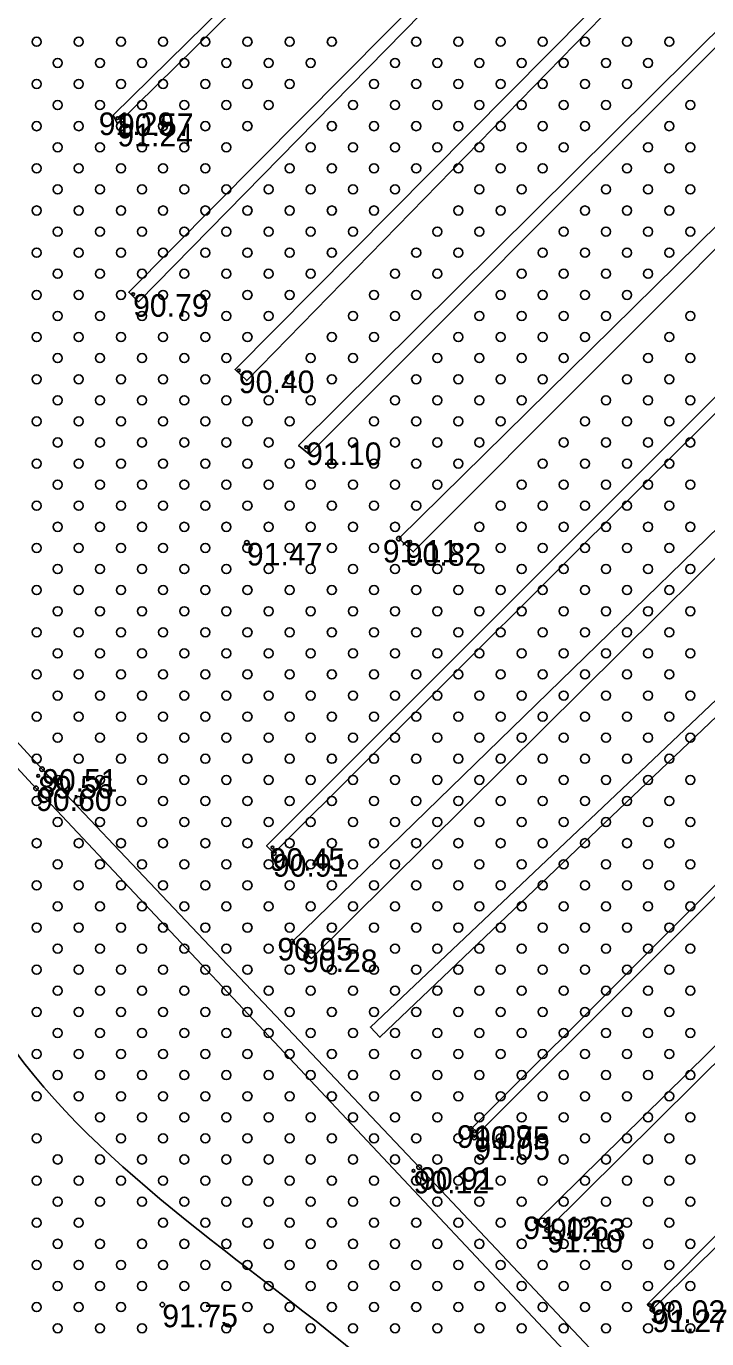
# Model space of a CAD drawing. Extents: x 316000 to 728450, y 314368 to 726000.
# Drawn here: x 725653.3 to 725766.2, y 315232.8 to 315450.6 of the extents above; entities that cross this region are included whole.
import ezdxf

# ---------------------------------------------------------------- set-up
doc = ezdxf.new("R2010")
doc.units = 0
for name, color, linetype in [('HIDG_ELEM_####_####_#', 7, 'Continuous'), ('HIDG_GRAV_####_####_#', 7, 'Continuous'), ('RELJ_AATZ_####_TKST_#', 7, 'Continuous'), ('RELJ_ELEM_####_####_#', 7, 'Continuous'), ('RELJ_HORZ_PAMT_####_#', 7, 'Continuous'), ('RELJ_NOGA_####_####_#', 7, 'Continuous'), ('TERT_ELEM_####_####_#', 7, 'Continuous')]:
    doc.layers.add(name, color=color, linetype=linetype)

msp = doc.modelspace()

# ---------------------------------------------------------------- linework, layer by layer
at = {"layer": 'HIDG_ELEM_####_####_#'}
for centre in [(725668.42, 315435.34), (725671.01, 315406.12), (725688.56, 315393.44), (725699.75, 315380.74), (725717, 315365.02), (725655.26, 315326.16), (725694.15, 315314.3), (725699.66, 315297.94), (725727.69, 315267.18), (725717.56, 315260.63), (725739.58, 315252.21), (725756.81, 315238.31)]:
    msp.add_circle(centre, 0.225, dxfattribs=at)
at = {"layer": 'HIDG_GRAV_####_####_#'}
for points in [[(725789.82, 315555.77), (725790.78, 315554.71), (725668.4, 315434.39), (725667.72, 315435.8), (725789.82, 315555.77)], [(725806.05, 315543.31), (725806.83, 315542.39), (725671.92, 315404.85), (725670.3, 315406.43), (725806.05, 315543.31)], [(725811.36, 315518.13), (725812.41, 315517.33), (725689.87, 315391.76), (725687.94, 315393.64), (725811.36, 315518.13)], [(725828.98, 315510.46), (725830.11, 315509.58), (725700.23, 315379.56), (725698.49, 315381.01), (725828.98, 315510.46)], [(725715.11, 315365.54), (725717.51, 315363.33), (725844.02, 315490.17), (725842.75, 315491.26), (725715.11, 315365.54)], [(725860.37, 315481.73), (725862.24, 315480.66), (725694.37, 315313.35), (725693.18, 315314.53), (725860.37, 315481.73)], [(725870.88, 315467.83), (725872.5, 315466.68), (725822.42, 315416.58), (725700.62, 315295.88), (725697.4, 315298.64), (725820.94, 315418.78), (725870.88, 315467.83)], [(725885.7, 315450.41), (725886.74, 315449.26), (725711.99, 315282.8), (725710.4, 315284.47), (725885.7, 315450.41)], [(725655.9, 315327.28), (725551.95, 315440.48)], [(725898.3, 315438.42), (725899.18, 315437.36), (725727.65, 315266.16), (725727.06, 315267.56), (725898.3, 315438.42)], [(725550.64, 315437.37), (725654.91, 315324.09), (725793.17, 315176.93), (726030.02, 314925.45), (726035.1, 314929.94), (725796.17, 315178.83)], [(725738.04, 315252.21), (725739.75, 315250.83), (725917.08, 315426.55), (725915.72, 315427.14), (725738.04, 315252.21)], [(725927.99, 315410.77), (725929.99, 315408.89), (725850.79, 315329.18), (725850.79, 315329.17), (725757.22, 315237.64), (725756.41, 315238.37), (725756.35, 315238.43), (725927.99, 315410.77)], [(725655.9, 315327.28), (725718.48, 315261.22), (725796.17, 315178.83)]]:
    msp.add_lwpolyline(points, dxfattribs=at)
at = {"layer": 'RELJ_ELEM_####_####_#'}
for centre in [(725689.89, 315364.84), (725715.11, 315365.54), (725655.9, 315327.28), (725654.91, 315324.09), (725694.37, 315313.35), (725697.4, 315298.64), (725727.06, 315267.56), (725727.65, 315266.16), (725718.48, 315261.22), (725738.04, 315252.21), (725739.75, 315250.83), (725675.86, 315238.41), (725757.19, 315237.6)]:
    msp.add_circle(centre, 0.375, dxfattribs=at)
at = {"layer": 'RELJ_HORZ_PAMT_####_#'}
msp.add_spline([(726081.57, 315247.05), (726057.5, 315241.5), (726036.5, 315213.5), (725977, 315161), (725966.5, 315108.5), (725903.5, 315045.5), (725862.12, 315076.6), (725805.5, 315130), (725759.7, 315178.88), (725709.89, 315228.8), (725646.99, 315287.19), (725634.68, 315314.96), (725629.04, 315327.48), (725557.35, 315340.26), (725478.3, 315344.16)], degree=3, dxfattribs=at)
at = {"layer": 'RELJ_NOGA_####_####_#'}
for points in [[(726259.12, 315084.51), (726262.72, 315089.26), (726261.56, 315090.84), (726260.2, 315092.42), (726257.29, 315095.53), (726218.91, 315136.38), (726180.31, 315176.84), (726128.67, 315229.97), (726063.7, 315298.11), (725999.9, 315366.09), (725937.21, 315432.09), (725876.35, 315495.23), (725810.58, 315563.08), (725744.7, 315632.91)], [(725740.86, 315626.98), (725805.54, 315558.12), (725870.39, 315491.15), (725932.8, 315426.8), (725994.98, 315360.84), (726059.66, 315292.12), (726075.75, 315275.46), (726092.08, 315259.04), (726108.47, 315242.67), (726124.69, 315226.14), (726193.27, 315154.03), (726250.06, 315092.6), (726256.32, 315085.83), (726258.82, 315084.29), (726259.12, 315084.51)]]:
    msp.add_spline(points, degree=3, dxfattribs=at)
at = {"layer": 'TERT_ELEM_####_####_#'}
for centre in [(725655, 315448), (725662, 315448), (725669, 315448), (725676, 315448), (725683, 315448), (725690, 315448), (725697, 315448), (725704, 315448), (725718, 315448), (725725, 315448), (725732, 315448), (725739, 315448), (725746, 315448), (725753, 315448), (725760, 315448), (725658.5, 315444.5), (725665.5, 315444.5), (725672.5, 315444.5), (725679.5, 315444.5), (725686.5, 315444.5), (725693.5, 315444.5), (725700.5, 315444.5), (725714.5, 315444.5), (725721.5, 315444.5), (725728.5, 315444.5), (725735.5, 315444.5), (725742.5, 315444.5), (725749.5, 315444.5), (725756.5, 315444.5), (725655, 315441), (725662, 315441), (725669, 315441), (725676, 315441), (725683, 315441), (725690, 315441), (725697, 315441), (725711, 315441), (725718, 315441), (725725, 315441), (725732, 315441), (725739, 315441), (725746, 315441), (725753, 315441), (725658.5, 315437.5), (725665.5, 315437.5), (725672.5, 315437.5), (725679.5, 315437.5), (725686.5, 315437.5), (725693.5, 315437.5), (725707.5, 315437.5), (725714.5, 315437.5), (725721.5, 315437.5), (725728.5, 315437.5), (725735.5, 315437.5), (725742.5, 315437.5), (725749.5, 315437.5), (725763.5, 315437.5), (725655, 315434), (725662, 315434), (725669, 315434), (725676, 315434), (725683, 315434), (725690, 315434), (725704, 315434), (725711, 315434), (725718, 315434), (725725, 315434), (725732, 315434), (725739, 315434), (725746, 315434), (725760, 315434), (725658.5, 315430.5), (725665.5, 315430.5), (725672.5, 315430.5), (725679.5, 315430.5), (725686.5, 315430.5), (725700.5, 315430.5), (725707.5, 315430.5), (725714.5, 315430.5), (725721.5, 315430.5), (725728.5, 315430.5), (725735.5, 315430.5), (725742.5, 315430.5), (725756.5, 315430.5), (725763.5, 315430.5), (725655, 315427), (725662, 315427), (725669, 315427), (725676, 315427), (725683, 315427), (725697, 315427), (725704, 315427), (725711, 315427), (725718, 315427), (725725, 315427), (725732, 315427), (725739, 315427), (725753, 315427), (725760, 315427), (725658.5, 315423.5), (725665.5, 315423.5), (725672.5, 315423.5), (725679.5, 315423.5), (725686.5, 315423.5), (725693.5, 315423.5), (725700.5, 315423.5), (725707.5, 315423.5), (725714.5, 315423.5), (725728.5, 315423.5), (725735.5, 315423.5), (725749.5, 315423.5), (725756.5, 315423.5), (725763.5, 315423.5), (725655, 315420), (725662, 315420), (725669, 315420), (725676, 315420), (725683, 315420), (725690, 315420), (725697, 315420), (725704, 315420), (725711, 315420), (725725, 315420), (725732, 315420), (725746, 315420), (725753, 315420), (725760, 315420), (725658.5, 315416.5), (725665.5, 315416.5), (725672.5, 315416.5), (725679.5, 315416.5), (725686.5, 315416.5), (725693.5, 315416.5), (725700.5, 315416.5), (725707.5, 315416.5), (725721.5, 315416.5), (725728.5, 315416.5), (725742.5, 315416.5), (725749.5, 315416.5), (725756.5, 315416.5), (725763.5, 315416.5), (725655, 315413), (725662, 315413), (725669, 315413), (725676, 315413), (725683, 315413), (725690, 315413), (725697, 315413), (725704, 315413), (725718, 315413), (725725, 315413), (725739, 315413), (725746, 315413), (725753, 315413), (725760, 315413), (725658.5, 315409.5), (725665.5, 315409.5), (725672.5, 315409.5), (725679.5, 315409.5), (725686.5, 315409.5), (725693.5, 315409.5), (725700.5, 315409.5), (725714.5, 315409.5), (725721.5, 315409.5), (725735.5, 315409.5), (725742.5, 315409.5), (725749.5, 315409.5), (725756.5, 315409.5), (725655, 315406), (725662, 315406), (725669, 315406), (725676, 315406), (725683, 315406), (725690, 315406), (725697, 315406), (725711, 315406), (725718, 315406), (725732, 315406), (725739, 315406), (725746, 315406), (725753, 315406), (725658.5, 315402.5), (725665.5, 315402.5), (725672.5, 315402.5), (725679.5, 315402.5), (725686.5, 315402.5), (725693.5, 315402.5), (725707.5, 315402.5), (725714.5, 315402.5), (725728.5, 315402.5), (725735.5, 315402.5), (725742.5, 315402.5), (725749.5, 315402.5), (725763.5, 315402.5), (725655, 315399), (725662, 315399), (725669, 315399), (725676, 315399), (725683, 315399), (725690, 315399), (725704, 315399), (725711, 315399), (725725, 315399), (725732, 315399), (725739, 315399), (725746, 315399), (725760, 315399), (725658.5, 315395.5), (725665.5, 315395.5), (725672.5, 315395.5), (725679.5, 315395.5), (725686.5, 315395.5), (725700.5, 315395.5), (725707.5, 315395.5), (725721.5, 315395.5), (725728.5, 315395.5), (725735.5, 315395.5), (725742.5, 315395.5), (725756.5, 315395.5), (725763.5, 315395.5), (725655, 315392), (725662, 315392), (725669, 315392), (725676, 315392), (725683, 315392), (725697, 315392), (725704, 315392), (725718, 315392), (725725, 315392), (725732, 315392), (725739, 315392), (725753, 315392), (725760, 315392), (725658.5, 315388.5), (725665.5, 315388.5), (725672.5, 315388.5), (725679.5, 315388.5), (725686.5, 315388.5), (725693.5, 315388.5), (725700.5, 315388.5), (725714.5, 315388.5), (725721.5, 315388.5), (725728.5, 315388.5), (725735.5, 315388.5), (725749.5, 315388.5), (725756.5, 315388.5), (725763.5, 315388.5), (725655, 315385), (725662, 315385), (725669, 315385), (725676, 315385), (725683, 315385), (725690, 315385), (725697, 315385), (725711, 315385), (725718, 315385), (725725, 315385), (725732, 315385), (725746, 315385), (725753, 315385), (725760, 315385), (725658.5, 315381.5), (725665.5, 315381.5), (725672.5, 315381.5), (725679.5, 315381.5), (725686.5, 315381.5), (725693.5, 315381.5), (725707.5, 315381.5), (725714.5, 315381.5), (725721.5, 315381.5), (725728.5, 315381.5), (725742.5, 315381.5), (725749.5, 315381.5), (725756.5, 315381.5), (725763.5, 315381.5), (725655, 315378), (725662, 315378), (725669, 315378), (725676, 315378), (725683, 315378), (725690, 315378), (725697, 315378), (725704, 315378), (725711, 315378), (725718, 315378), (725725, 315378), (725739, 315378), (725746, 315378), (725753, 315378), (725760, 315378), (725658.5, 315374.5), (725665.5, 315374.5), (725672.5, 315374.5), (725679.5, 315374.5), (725686.5, 315374.5), (725693.5, 315374.5), (725700.5, 315374.5), (725707.5, 315374.5), (725714.5, 315374.5), (725721.5, 315374.5), (725735.5, 315374.5), (725742.5, 315374.5), (725749.5, 315374.5), (725756.5, 315374.5), (725763.5, 315374.5), (725655, 315371), (725662, 315371), (725669, 315371), (725676, 315371), (725683, 315371), (725690, 315371), (725697, 315371), (725704, 315371), (725711, 315371), (725718, 315371), (725732, 315371), (725739, 315371), (725746, 315371), (725753, 315371), (725760, 315371), (725658.5, 315367.5), (725665.5, 315367.5), (725672.5, 315367.5), (725679.5, 315367.5), (725686.5, 315367.5), (725693.5, 315367.5), (725700.5, 315367.5), (725707.5, 315367.5), (725714.5, 315367.5), (725728.5, 315367.5), (725735.5, 315367.5), (725742.5, 315367.5), (725749.5, 315367.5), (725756.5, 315367.5), (725763.5, 315367.5), (725655, 315364), (725662, 315364), (725669, 315364), (725676, 315364), (725683, 315364), (725690, 315364), (725697, 315364), (725704, 315364), (725711, 315364), (725725, 315364), (725732, 315364), (725739, 315364), (725746, 315364), (725753, 315364), (725760, 315364), (725658.5, 315360.5), (725665.5, 315360.5), (725672.5, 315360.5), (725679.5, 315360.5), (725686.5, 315360.5), (725693.5, 315360.5), (725700.5, 315360.5), (725707.5, 315360.5), (725714.5, 315360.5), (725721.5, 315360.5), (725728.5, 315360.5), (725735.5, 315360.5), (725742.5, 315360.5), (725749.5, 315360.5), (725756.5, 315360.5), (725763.5, 315360.5), (725655, 315357), (725662, 315357), (725669, 315357), (725676, 315357), (725683, 315357), (725690, 315357), (725697, 315357), (725704, 315357), (725711, 315357), (725718, 315357), (725725, 315357), (725732, 315357), (725739, 315357), (725746, 315357), (725753, 315357), (725760, 315357), (725658.5, 315353.5), (725665.5, 315353.5), (725672.5, 315353.5), (725679.5, 315353.5), (725686.5, 315353.5), (725693.5, 315353.5), (725700.5, 315353.5), (725707.5, 315353.5), (725714.5, 315353.5), (725721.5, 315353.5), (725728.5, 315353.5), (725735.5, 315353.5), (725742.5, 315353.5), (725749.5, 315353.5), (725756.5, 315353.5), (725763.5, 315353.5), (725655, 315350), (725662, 315350), (725669, 315350), (725676, 315350), (725683, 315350), (725690, 315350), (725697, 315350), (725704, 315350), (725711, 315350), (725718, 315350), (725725, 315350), (725732, 315350), (725739, 315350), (725746, 315350), (725753, 315350), (725760, 315350), (725658.5, 315346.5), (725665.5, 315346.5), (725672.5, 315346.5), (725679.5, 315346.5), (725686.5, 315346.5), (725693.5, 315346.5), (725700.5, 315346.5), (725707.5, 315346.5), (725714.5, 315346.5), (725721.5, 315346.5), (725728.5, 315346.5), (725735.5, 315346.5), (725742.5, 315346.5), (725749.5, 315346.5), (725756.5, 315346.5), (725763.5, 315346.5), (725655, 315343), (725662, 315343), (725669, 315343), (725676, 315343), (725683, 315343), (725690, 315343), (725697, 315343), (725704, 315343), (725711, 315343), (725718, 315343), (725725, 315343), (725732, 315343), (725739, 315343), (725746, 315343), (725753, 315343), (725760, 315343), (725658.5, 315339.5), (725665.5, 315339.5), (725672.5, 315339.5), (725679.5, 315339.5), (725686.5, 315339.5), (725693.5, 315339.5), (725700.5, 315339.5), (725707.5, 315339.5), (725714.5, 315339.5), (725721.5, 315339.5), (725728.5, 315339.5), (725735.5, 315339.5), (725742.5, 315339.5), (725749.5, 315339.5), (725756.5, 315339.5), (725763.5, 315339.5), (725655, 315336), (725662, 315336), (725669, 315336), (725676, 315336), (725683, 315336), (725690, 315336), (725697, 315336), (725704, 315336), (725711, 315336), (725718, 315336), (725725, 315336), (725732, 315336), (725739, 315336), (725746, 315336), (725753, 315336), (725760, 315336), (725658.5, 315332.5), (725665.5, 315332.5), (725672.5, 315332.5), (725679.5, 315332.5), (725686.5, 315332.5), (725693.5, 315332.5), (725700.5, 315332.5), (725707.5, 315332.5), (725714.5, 315332.5), (725721.5, 315332.5), (725728.5, 315332.5), (725735.5, 315332.5), (725742.5, 315332.5), (725749.5, 315332.5), (725756.5, 315332.5), (725763.5, 315332.5), (725655, 315329), (725662, 315329), (725669, 315329), (725676, 315329), (725683, 315329), (725690, 315329), (725697, 315329), (725704, 315329), (725711, 315329), (725718, 315329), (725725, 315329), (725732, 315329), (725739, 315329), (725746, 315329), (725753, 315329), (725760, 315329), (725658.5, 315325.5), (725665.5, 315325.5), (725672.5, 315325.5), (725679.5, 315325.5), (725686.5, 315325.5), (725693.5, 315325.5), (725700.5, 315325.5), (725707.5, 315325.5), (725714.5, 315325.5), (725721.5, 315325.5), (725728.5, 315325.5), (725735.5, 315325.5), (725742.5, 315325.5), (725749.5, 315325.5), (725756.5, 315325.5), (725763.5, 315325.5), (725655, 315322), (725662, 315322), (725669, 315322), (725676, 315322), (725683, 315322), (725690, 315322), (725697, 315322), (725704, 315322), (725711, 315322), (725718, 315322), (725725, 315322), (725732, 315322), (725739, 315322), (725746, 315322), (725753, 315322), (725760, 315322), (725658.5, 315318.5), (725665.5, 315318.5), (725672.5, 315318.5), (725679.5, 315318.5), (725686.5, 315318.5), (725693.5, 315318.5), (725700.5, 315318.5), (725707.5, 315318.5), (725714.5, 315318.5), (725721.5, 315318.5), (725728.5, 315318.5), (725735.5, 315318.5), (725742.5, 315318.5), (725749.5, 315318.5), (725756.5, 315318.5), (725763.5, 315318.5), (725655, 315315), (725662, 315315), (725669, 315315), (725676, 315315), (725683, 315315), (725690, 315315), (725697, 315315), (725704, 315315), (725711, 315315), (725718, 315315), (725725, 315315), (725732, 315315), (725739, 315315), (725746, 315315), (725753, 315315), (725760, 315315), (725658.5, 315311.5), (725665.5, 315311.5), (725672.5, 315311.5), (725679.5, 315311.5), (725686.5, 315311.5), (725693.5, 315311.5), (725700.5, 315311.5), (725707.5, 315311.5), (725714.5, 315311.5), (725721.5, 315311.5), (725728.5, 315311.5), (725735.5, 315311.5), (725742.5, 315311.5), (725749.5, 315311.5), (725756.5, 315311.5), (725763.5, 315311.5), (725655, 315308), (725662, 315308), (725669, 315308), (725676, 315308), (725683, 315308), (725690, 315308), (725697, 315308), (725704, 315308), (725711, 315308), (725718, 315308), (725725, 315308), (725732, 315308), (725739, 315308), (725746, 315308), (725753, 315308), (725760, 315308), (725658.5, 315304.5), (725665.5, 315304.5), (725672.5, 315304.5), (725679.5, 315304.5), (725686.5, 315304.5), (725693.5, 315304.5), (725700.5, 315304.5), (725707.5, 315304.5), (725714.5, 315304.5), (725721.5, 315304.5), (725728.5, 315304.5), (725735.5, 315304.5), (725742.5, 315304.5), (725749.5, 315304.5), (725756.5, 315304.5), (725763.5, 315304.5), (725655, 315301), (725662, 315301), (725669, 315301), (725676, 315301), (725683, 315301), (725690, 315301), (725697, 315301), (725704, 315301), (725711, 315301), (725718, 315301), (725725, 315301), (725732, 315301), (725739, 315301), (725746, 315301), (725753, 315301), (725760, 315301), (725658.5, 315297.5), (725665.5, 315297.5), (725672.5, 315297.5), (725679.5, 315297.5), (725686.5, 315297.5), (725693.5, 315297.5), (725700.5, 315297.5), (725707.5, 315297.5), (725714.5, 315297.5), (725721.5, 315297.5), (725728.5, 315297.5), (725735.5, 315297.5), (725742.5, 315297.5), (725749.5, 315297.5), (725756.5, 315297.5), (725763.5, 315297.5), (725655, 315294), (725662, 315294), (725669, 315294), (725676, 315294), (725683, 315294), (725690, 315294), (725697, 315294), (725704, 315294), (725711, 315294), (725718, 315294), (725725, 315294), (725732, 315294), (725739, 315294), (725746, 315294), (725753, 315294), (725760, 315294), (725658.5, 315290.5), (725665.5, 315290.5), (725672.5, 315290.5), (725679.5, 315290.5), (725686.5, 315290.5), (725693.5, 315290.5), (725700.5, 315290.5), (725707.5, 315290.5), (725714.5, 315290.5), (725721.5, 315290.5), (725728.5, 315290.5), (725735.5, 315290.5), (725742.5, 315290.5), (725749.5, 315290.5), (725756.5, 315290.5), (725763.5, 315290.5), (725655, 315287), (725662, 315287), (725669, 315287), (725676, 315287), (725683, 315287), (725690, 315287), (725697, 315287), (725704, 315287), (725711, 315287), (725718, 315287), (725725, 315287), (725732, 315287), (725739, 315287), (725746, 315287), (725753, 315287), (725760, 315287), (725658.5, 315283.5), (725665.5, 315283.5), (725672.5, 315283.5), (725679.5, 315283.5), (725686.5, 315283.5), (725693.5, 315283.5), (725700.5, 315283.5), (725707.5, 315283.5), (725714.5, 315283.5), (725721.5, 315283.5), (725728.5, 315283.5), (725735.5, 315283.5), (725742.5, 315283.5), (725749.5, 315283.5), (725756.5, 315283.5), (725763.5, 315283.5), (725655, 315280), (725662, 315280), (725669, 315280), (725676, 315280), (725683, 315280), (725690, 315280), (725697, 315280), (725704, 315280), (725711, 315280), (725718, 315280), (725725, 315280), (725732, 315280), (725739, 315280), (725746, 315280), (725753, 315280), (725760, 315280), (725658.5, 315276.5), (725665.5, 315276.5), (725672.5, 315276.5), (725679.5, 315276.5), (725686.5, 315276.5), (725693.5, 315276.5), (725700.5, 315276.5), (725707.5, 315276.5), (725714.5, 315276.5), (725721.5, 315276.5), (725728.5, 315276.5), (725735.5, 315276.5), (725742.5, 315276.5), (725749.5, 315276.5), (725756.5, 315276.5), (725763.5, 315276.5), (725655, 315273), (725662, 315273), (725669, 315273), (725676, 315273), (725683, 315273), (725690, 315273), (725697, 315273), (725704, 315273), (725711, 315273), (725718, 315273), (725725, 315273), (725732, 315273), (725739, 315273), (725746, 315273), (725753, 315273), (725760, 315273), (725665.5, 315269.5), (725672.5, 315269.5), (725679.5, 315269.5), (725686.5, 315269.5), (725693.5, 315269.5), (725700.5, 315269.5), (725707.5, 315269.5), (725714.5, 315269.5), (725721.5, 315269.5), (725728.5, 315269.5), (725735.5, 315269.5), (725742.5, 315269.5), (725749.5, 315269.5), (725756.5, 315269.5), (725763.5, 315269.5), (725655, 315266), (725669, 315266), (725676, 315266), (725683, 315266), (725690, 315266), (725697, 315266), (725704, 315266), (725711, 315266), (725718, 315266), (725725, 315266), (725732, 315266), (725739, 315266), (725746, 315266), (725753, 315266), (725760, 315266), (725658.5, 315262.5), (725665.5, 315262.5), (725672.5, 315262.5), (725679.5, 315262.5), (725686.5, 315262.5), (725693.5, 315262.5), (725700.5, 315262.5), (725707.5, 315262.5), (725714.5, 315262.5), (725721.5, 315262.5), (725728.5, 315262.5), (725735.5, 315262.5), (725742.5, 315262.5), (725749.5, 315262.5), (725756.5, 315262.5), (725763.5, 315262.5), (725655, 315259), (725662, 315259), (725669, 315259), (725676, 315259), (725683, 315259), (725690, 315259), (725697, 315259), (725704, 315259), (725711, 315259), (725718, 315259), (725725, 315259), (725732, 315259), (725739, 315259), (725746, 315259), (725753, 315259), (725760, 315259), (725658.5, 315255.5), (725665.5, 315255.5), (725672.5, 315255.5), (725679.5, 315255.5), (725686.5, 315255.5), (725693.5, 315255.5), (725700.5, 315255.5), (725707.5, 315255.5), (725714.5, 315255.5), (725721.5, 315255.5), (725728.5, 315255.5), (725735.5, 315255.5), (725742.5, 315255.5), (725749.5, 315255.5), (725756.5, 315255.5), (725763.5, 315255.5), (725655, 315252), (725662, 315252), (725676, 315252), (725683, 315252), (725690, 315252), (725697, 315252), (725704, 315252), (725711, 315252), (725718, 315252), (725725, 315252), (725732, 315252), (725739, 315252), (725746, 315252), (725753, 315252), (725760, 315252), (725658.5, 315248.5), (725665.5, 315248.5), (725672.5, 315248.5), (725679.5, 315248.5), (725686.5, 315248.5), (725693.5, 315248.5), (725700.5, 315248.5), (725707.5, 315248.5), (725714.5, 315248.5), (725721.5, 315248.5), (725728.5, 315248.5), (725735.5, 315248.5), (725742.5, 315248.5), (725749.5, 315248.5), (725756.5, 315248.5), (725763.5, 315248.5), (725655, 315245), (725662, 315245), (725669, 315245), (725676, 315245), (725683, 315245), (725690, 315245), (725697, 315245), (725704, 315245), (725711, 315245), (725718, 315245), (725725, 315245), (725732, 315245), (725739, 315245), (725746, 315245), (725753, 315245), (725760, 315245), (725658.5, 315241.5), (725665.5, 315241.5), (725672.5, 315241.5), (725679.5, 315241.5), (725686.5, 315241.5), (725693.5, 315241.5), (725700.5, 315241.5), (725707.5, 315241.5), (725714.5, 315241.5), (725721.5, 315241.5), (725728.5, 315241.5), (725735.5, 315241.5), (725742.5, 315241.5), (725749.5, 315241.5), (725756.5, 315241.5), (725763.5, 315241.5), (725655, 315238), (725662, 315238), (725669, 315238), (725683, 315238), (725690, 315238), (725697, 315238), (725704, 315238), (725711, 315238), (725718, 315238), (725725, 315238), (725732, 315238), (725739, 315238), (725746, 315238), (725753, 315238), (725760, 315238), (725658.5, 315234.5), (725665.5, 315234.5), (725672.5, 315234.5), (725686.5, 315234.5), (725693.5, 315234.5), (725700.5, 315234.5), (725707.5, 315234.5), (725714.5, 315234.5), (725721.5, 315234.5), (725728.5, 315234.5), (725735.5, 315234.5), (725742.5, 315234.5), (725749.5, 315234.5), (725756.5, 315234.5), (725763.5, 315234.5)]:
    msp.add_circle(centre, 0.75, dxfattribs=at)

# ---------------------------------------------------------------- texts
at = {"layer": 'RELJ_AATZ_####_TKST_#'}
for s, p in [('91.29', (725665.31, 315432.52)), ('90.57', (725668.5, 315432.35)), ('91.24', (725668.4, 315430.64)), ('90.79', (725671.01, 315402.37)), ('90.40', (725688.56, 315389.69)), ('91.10', (725699.72, 315377.76)), ('91.47', (725689.89, 315361.09)), ('91.11', (725712.46, 315361.59)), ('90.82', (725716.26, 315361.04)), ('90.51', (725655.9, 315323.54)), ('89.56', (725655.26, 315322.41)), ('90.60', (725654.91, 315320.34)), ('90.45', (725693.66, 315310.42)), ('90.91', (725694.21, 315309.44)), ('90.95', (725694.96, 315295.53)), ('90.28', (725699.04, 315293.6)), ('91.09', (725724.76, 315264.43)), ('90.75', (725727.61, 315264.24)), ('91.05', (725727.65, 315262.41)), ('90.12', (725717.56, 315256.88)), ('90.91', (725718.48, 315257.47)), ('91.12', (725735.78, 315249.28)), ('91.10', (725739.75, 315247.08)), ('90.63', (725740.22, 315248.95)), ('91.75', (725675.86, 315234.66)), ('90.02', (725756.75, 315235.38)), ('91.27', (725757.19, 315233.85))]:
    msp.add_text(s, height=3.75, dxfattribs=at).set_placement(p)

doc.saveas('drawing.dxf')
